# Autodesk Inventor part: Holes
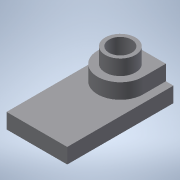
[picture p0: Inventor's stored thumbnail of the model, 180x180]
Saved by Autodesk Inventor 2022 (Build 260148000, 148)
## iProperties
Created: 2013-12
Part Number: Holes
Material: Generic
Document SubType Name: Modeling
Designer: John
Density: 1 g/cm^3
Appearance: Default
Author: John
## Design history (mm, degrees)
sketch "Sketch1"
  geometry: L1 (0, 0)-(-50.8, 0); L2 (-50.8, 0)-(-50.8, -88.9); L3 (-50.8, -88.9)-(0, -88.9); L4 (0, -88.9)-(0, 0)
  constraints: 8 end point, 2 parallel, 1 horizontal, 1 perpendicular
  dimensions: "d0" = 50.8 distance of L3.end L2.end; "d1" = 88.9 distance of L2.end L1.end
extrude "Extrusion1" new body sketch "Sketch1" distance "d2" = 12.7; taper "d3" = 0 deg
sketch "Sketch2"
  geometry: L1 (50.8, 0)-(50.8, 88.9) reference; L2 (50.8, 88.9)-(0, 88.9) reference; L3 (0, 88.9)-(0, 0) reference; L4 (6.35, 88.9)-(44.45, 88.9); L5 (44.45, 88.9)-(44.45, 69.85); L6 (44.45, 69.85)-(6.35, 69.85); L7 (6.35, 69.85)-(6.35, 88.9); L8 (6.35, 79.375)-(0, 79.375); L9 (44.45, 79.375)-(50.8, 79.375); 1 further point
  constraints: 12 end point, 3 midpoint, 3 perpendicular, 3 point on line, 2 parallel, 1 collinear, 1 horizontal, 1 horizontal alignment, 2 other
  dimensions: "d4" = 19.05 distance of L4.end L5.end; "d5" = 6.35 distance between parallel lines of L3 L7
extrude "Extrusion2" join sketch "Sketch2" distance "d6" = 12.7; taper "d7" = 0 deg
sketch "Sketch3"
  geometry: C1 r 12.7 at (25.4, 69.85); A1 r 19.05 centre (25.4, 69.85) between (6.35, 69.85) and (44.45, 69.85) reference; 1 further point
  constraints: 1 centre point, 1 coincident
  dimensions: "d8" = 25.4 diameter of C1
extrude "Extrusion3" join sketch "Sketch3" distance "d9" = 12.7; taper "d10" = 0 deg
sketch "Sketch6"
  geometry: L1 (44.45, 88.9)-(44.45, 69.85) reference; L2 (6.35, 69.85)-(6.35, 88.9) reference; L3 (6.35, 88.9)-(0, 88.9) reference; L4 (0, 88.9)-(0, 0) reference; L5 (0, 0)-(50.8, 0) reference; L6 (50.8, 0)-(50.8, 88.9) reference; L7 (50.8, 88.9)-(44.45, 88.9) reference; L8 (44.45, 88.9)-(44.45, 6.35); L9 (44.45, 6.35)-(6.35, 6.35); L10 (6.35, 6.35)-(6.35, 88.9); L11 (6.35, 38.1)-(44.45, 38.1); A1 r 19.05 centre (25.4, 69.85) between (6.35, 69.85) and (44.45, 69.85) reference
  constraints: 8 end point, 2 point on line, 1 perpendicular, 2 other
  dimensions: "d35" = 6.35 distance between parallel lines of L5 L9; "d36" = 31.75 distance between parallel lines of L9 L11
sketch "Sketch7"
  geometry: C1 r 12.7 at (0, 0) reference; 2 further points
  constraints: 1 coincident
hole "Hole3" sketch "Sketch7" at (0, 0) diameter "d37" = 19.05; stored, may be unused: countersink angle "d41" = 82 deg, drill point angle "d43" = 118 deg; dims "d38" = 19.05, "d39" = 4.7625, "d40" = 6.35, "d42" = 25.4
body "Solid1"
